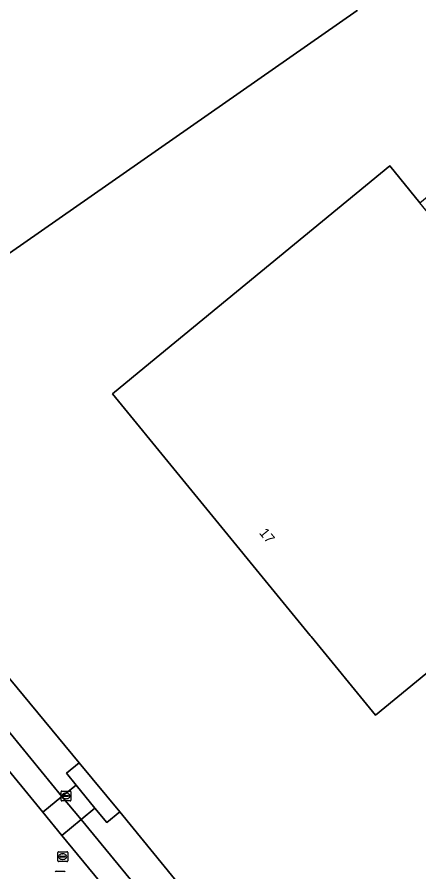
# Model space of a CAD drawing. Extents: x 156702 to 158052, y 387630 to 388992.
# Drawn here: x 157195.1 to 157235.7, y 387837.2 to 387923.6 of the extents above; entities that cross this region are included whole.
import ezdxf

# ---------------------------------------------------------------- set-up
doc = ezdxf.new("R2010")
doc.units = 0
for name, color, linetype in [('IMGEO_Brandkraan', 7, 'Continuous'), ('IMGEO_Erf', 7, 'Continuous'), ('IMGEO_Groenvoorziening', 7, 'Continuous'), ('IMGEO_Pand', 7, 'Continuous'), ('IMGEO_Pand_nummerreeks', 7, 'Continuous'), ('IMGEO_Parkeervlak_open', 7, 'Continuous'), ('IMGEO_Rijbaan_lokaal_gesloten', 7, 'Continuous'), ('IMGEO_Rioolput', 7, 'Continuous'), ('IMGEO_Voetpad_open', 7, 'Continuous')]:
    doc.layers.add(name, color=color, linetype=linetype)

msp = doc.modelspace()

# ---------------------------------------------------------------- linework, layer by layer
at = {"layer": 'IMGEO_Brandkraan'}
for p, q in [((157199.528, 387844.428), (157199.528, 387845.28)), ((157199.603, 387845.354), (157200.455, 387845.354)), ((157199.787, 387844.848), (157199.787, 387844.86)), ((157200.225, 387844.811), (157199.827, 387844.811)), ((157199.83, 387844.897), (157200.228, 387844.897)), ((157200.016, 387845.134), (157200.041, 387845.134)), ((157200.271, 387844.86), (157200.271, 387844.848)), ((157200.529, 387845.28), (157200.529, 387844.428)), ((157200.455, 387844.354), (157199.603, 387844.354)), ((157200.039, 387844.574), (157200.014, 387844.574))]:
    msp.add_line(p, q, dxfattribs=at)
for points in [[(157199.528, 387844.428), (157199.528, 387845.28)], [(157199.603, 387845.354), (157200.455, 387845.354)], [(157200.529, 387845.28), (157200.529, 387844.428)], [(157200.455, 387844.354), (157199.603, 387844.354)]]:
    msp.add_lwpolyline(points, dxfattribs=at)
for centre, radius, start, end in [((157199.605, 387845.278), 0.0765, 91.55205, 178.44795), ((157199.605, 387845.278), 0.0765, 91.55205, 178.44795), ((157199.827, 387844.857), 0.0403, 85.87752, 175.75265), ((157199.824, 387844.847), 0.0366, 178.93798, 274.71019), ((157200.228, 387844.854), 0.043, 264.86636, 352.45326), ((157200.232, 387844.859), 0.0386, 1.73085, 96.63898), ((157200.453, 387845.278), 0.0765, 1.55205, 88.44795), ((157200.453, 387845.278), 0.0765, 1.55205, 88.44795), ((157199.605, 387844.43), 0.0765, 181.55205, 268.44795), ((157199.605, 387844.43), 0.0765, 181.55205, 268.44795), ((157200.453, 387844.43), 0.0765, 271.55205, 358.44795), ((157200.453, 387844.43), 0.0765, 271.55205, 358.44795)]:
    msp.add_arc(centre, radius, start, end, dxfattribs=at)
for centre, major_axis, ratio, start_param, end_param in [((157200.015, 387844.854), (-0.387, 0.002), 0.722429, 4.712389, 7.853982), ((157200.04, 387844.854), (-0.39, 0.002), 0.717154, 1.570796, 4.712389)]:
    msp.add_ellipse(centre, major_axis=major_axis, ratio=ratio, start_param=start_param, end_param=end_param, dxfattribs=at)
at = {"layer": 'IMGEO_Erf'}
for points in [[(157229.485, 387924.241), (157192.497, 387898.477), (157188.394, 387895.619), (157186.26, 387898.688), (157181.336, 387905.773), (157180.619, 387905.271), (157180.691, 387905.145), (157180.445, 387904.939), (157177.073, 387908.979), (157177.382, 387909.273), (157174.943, 387912.73), (157174.366, 387912.233), (157170.986, 387916.283), (157171.224, 387916.486), (157171.368, 387916.347), (157173.137, 387917.581), (157168.679, 387924.016), (157168.522, 387924.242), (157165.537, 387928.552), (157165.475, 387928.641), (157169.584, 387931.491), (157206.576, 387957.146)], [(157277.793, 387899.706), (157280.965, 387895.842), (157269.653, 387886.542), (157258.413, 387877.301), (157259.351, 387876.158), (157259.415, 387876.08), (157231.347, 387853.023), (157224.82, 387860.984), (157224.742, 387861.079), (157211.242, 387877.546), (157204.726, 387885.494), (157208.589, 387888.669), (157232.772, 387908.543), (157235.822, 387904.802), (157247.12, 387914.055), (157258.419, 387923.308)]]:
    msp.add_lwpolyline(points, close=True, dxfattribs=at)
msp.add_lwpolyline([(157113.203, 387955.403), (157114.82, 387953.45), (157124.927, 387941.131), (157130.787, 387933.959), (157141.556, 387921.139), (157154.783, 387905.136), (157179.278, 387874.935), (157184.134, 387869.06), (157193.638, 387857.523), (157201.348, 387848.217), (157205.459, 387843.261), (157211.007, 387836.491), (157224.534, 387819.949), (157225.552, 387818.74), (157225.932, 387819.031), (157231.711, 387812.018), (157231.33, 387811.708), (157232.256, 387810.596), (157241.527, 387799.34), (157241.633, 387799.436), (157243.736, 387796.79), (157248.763, 387790.697), (157254.703, 387783.586)], dxfattribs=at)
at = {"layer": 'IMGEO_Groenvoorziening'}
msp.add_lwpolyline([(157205.459, 387843.261), (157201.348, 387848.217), (157200.063, 387847.163), (157201.058, 387845.959), (157202.94, 387843.604), (157204.149, 387842.176)], close=True, dxfattribs=at)
at = {"layer": 'IMGEO_Pand'}
for points in [[(157192.497, 387898.477), (157229.485, 387924.241), (157206.576, 387957.146), (157169.584, 387931.491), (157165.475, 387928.641), (157165.537, 387928.552), (157168.522, 387924.242), (157168.679, 387924.016), (157173.137, 387917.581), (157171.368, 387916.347), (157171.224, 387916.486), (157170.986, 387916.283), (157174.366, 387912.233), (157174.943, 387912.73), (157177.382, 387909.273), (157177.073, 387908.979), (157180.445, 387904.939), (157180.691, 387905.145), (157180.619, 387905.271), (157181.336, 387905.773), (157186.26, 387898.688), (157188.394, 387895.619)], [(157235.822, 387904.802), (157232.772, 387908.543), (157208.589, 387888.669), (157204.726, 387885.494), (157211.242, 387877.546), (157224.742, 387861.079), (157224.82, 387860.984), (157231.347, 387853.023), (157259.415, 387876.08), (157259.351, 387876.158), (157258.413, 387877.301)]]:
    msp.add_lwpolyline(points, close=True, dxfattribs=at)
at = {"layer": 'IMGEO_Parkeervlak_open'}
msp.add_lwpolyline([(157199.62, 387844.8), (157197.685, 387843.207), (157199.612, 387840.866), (157201.559, 387842.468)], close=True, dxfattribs=at)
at = {"layer": 'IMGEO_Rijbaan_lokaal_gesloten'}
msp.add_lwpolyline([(157287.519, 387734.083), (157277.976, 387745.688), (157269.346, 387756.182), (157269.017, 387756.61), (157251.891, 387777.753), (157250.98, 387778.606), (157249.988, 387779.667), (157249.839, 387779.847), (157244.871, 387785.883), (157238.562, 387793.548), (157237.294, 387795.089), (157230.307, 387803.576), (157228.911, 387805.272), (157218.718, 387817.655), (157207.869, 387830.835), (157199.612, 387840.866), (157197.685, 387843.207), (157188.201, 387854.729), (157180.575, 387863.993), (157173.658, 387872.397), (157168.303, 387867.992), (157244.684, 387775.137), (157337.844, 387661.887)], dxfattribs=at)
at = {"layer": 'IMGEO_Rioolput'}
for p, q in [((157199.199, 387838.294), (157199.199, 387839.146)), ((157199.274, 387839.22), (157200.126, 387839.22)), ((157199.501, 387838.763), (157199.899, 387838.763)), ((157199.687, 387839), (157199.712, 387839)), ((157200.2, 387839.146), (157200.2, 387838.294)), ((157200.126, 387838.22), (157199.274, 387838.22)), ((157199.458, 387838.714), (157199.458, 387838.726)), ((157199.896, 387838.677), (157199.498, 387838.677)), ((157199.71, 387838.44), (157199.685, 387838.44)), ((157199.942, 387838.726), (157199.942, 387838.714)), ((157199.019, 387837.251), (157199.871, 387837.251))]:
    msp.add_line(p, q, dxfattribs=at)
for points in [[(157199.199, 387838.294), (157199.199, 387839.146)], [(157199.274, 387839.22), (157200.126, 387839.22)], [(157200.2, 387839.146), (157200.2, 387838.294)], [(157200.126, 387838.22), (157199.274, 387838.22)], [(157199.019, 387837.251), (157199.871, 387837.251)]]:
    msp.add_lwpolyline(points, dxfattribs=at)
for centre, radius, start, end in [((157199.276, 387839.144), 0.0765, 91.55205, 178.44795), ((157199.276, 387839.144), 0.0765, 91.55205, 178.44795), ((157199.498, 387838.723), 0.0403, 85.87752, 175.75265), ((157199.903, 387838.725), 0.0386, 1.73085, 96.63898), ((157200.124, 387839.144), 0.0765, 1.55205, 88.44795), ((157200.124, 387839.144), 0.0765, 1.55205, 88.44795), ((157199.276, 387838.296), 0.0765, 181.55205, 268.44795), ((157199.276, 387838.296), 0.0765, 181.55205, 268.44795), ((157199.495, 387838.713), 0.0366, 178.93798, 274.71019), ((157199.899, 387838.72), 0.043, 264.86636, 352.45326), ((157200.124, 387838.296), 0.0765, 271.55205, 358.44795), ((157200.124, 387838.296), 0.0765, 271.55205, 358.44795), ((157199.021, 387837.175), 0.0765, 91.55205, 178.44795), ((157199.021, 387837.175), 0.0765, 91.55205, 178.44795), ((157199.869, 387837.175), 0.0765, 1.55205, 88.44795), ((157199.869, 387837.175), 0.0765, 1.55205, 88.44795)]:
    msp.add_arc(centre, radius, start, end, dxfattribs=at)
for centre, major_axis, ratio, start_param, end_param in [((157199.686, 387838.72), (-0.387, 0.002), 0.722429, 4.712389, 7.853982), ((157199.711, 387838.72), (-0.39, 0.002), 0.717154, 1.570796, 4.712389)]:
    msp.add_ellipse(centre, major_axis=major_axis, ratio=ratio, start_param=start_param, end_param=end_param, dxfattribs=at)
at = {"layer": 'IMGEO_Voetpad_open'}
for points in [[(157199.62, 387844.8), (157201.058, 387845.959), (157200.063, 387847.163), (157201.348, 387848.217), (157193.638, 387857.523), (157192.399, 387856.443), (157191.524, 387857.463), (157190.148, 387856.329)], [(157190.148, 387856.329), (157188.201, 387854.729), (157197.685, 387843.207), (157199.62, 387844.8)], [(157201.559, 387842.468), (157202.94, 387843.604), (157201.058, 387845.959), (157199.62, 387844.8)], [(157209.816, 387832.438), (157211.184, 387833.607), (157209.688, 387835.425), (157211.007, 387836.491), (157205.459, 387843.261), (157204.149, 387842.176), (157202.94, 387843.604), (157201.559, 387842.468)], [(157201.559, 387842.468), (157199.612, 387840.866), (157207.869, 387830.835), (157209.816, 387832.438)]]:
    msp.add_lwpolyline(points, close=True, dxfattribs=at)

# ---------------------------------------------------------------- texts
at = {"layer": 'IMGEO_Pand_nummerreeks'}
msp.add_text('17', height=1, rotation=309.3448, dxfattribs=at).set_placement((157219.519, 387871.425))

doc.saveas('drawing.dxf')
